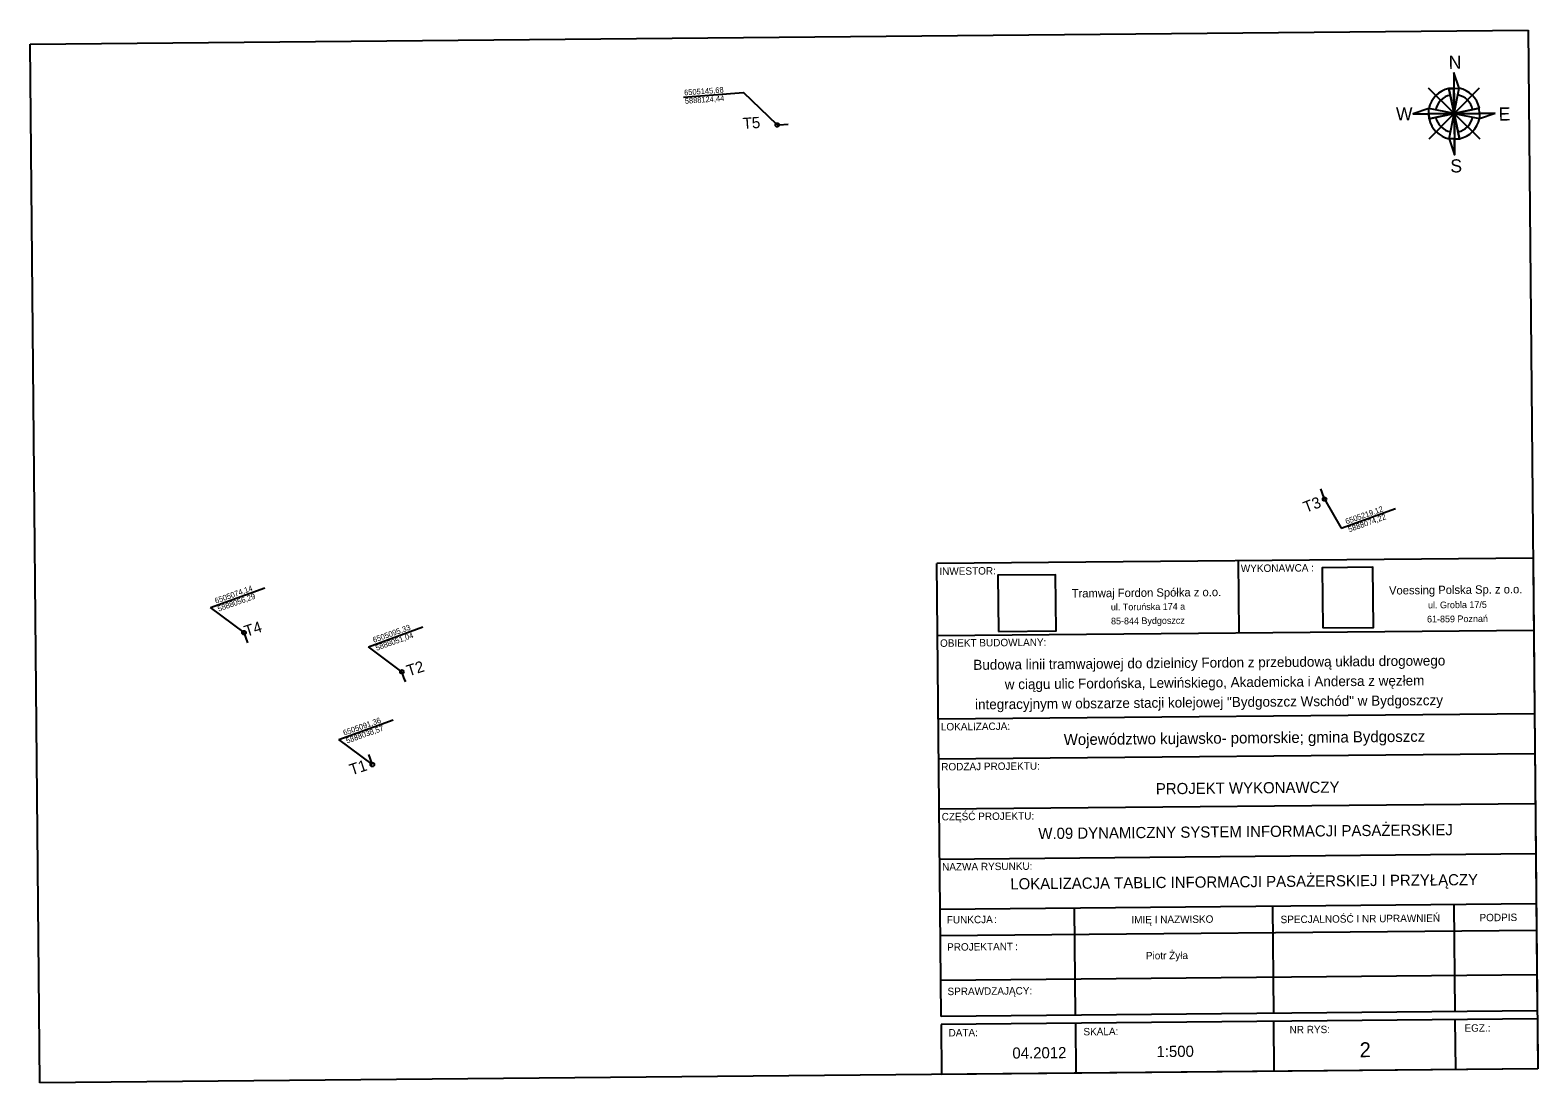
# Model space of a CAD drawing. Extents: x 6505045 to 6511721, y 5887996 to 5893535.
# Drawn here: x 6505045.4 to 6505247.7, y 5887995.8 to 5888137.2 of the extents above; entities that cross this region are included whole.
import ezdxf

# ---------------------------------------------------------------- set-up
doc = ezdxf.new("R2010")
doc.units = 0
for name, color, linetype in [('__legenda', 7, 'Continuous'), ('Default', 7, 'Continuous'), ('P_2 tablice LCD', 7, 'Continuous'), ('P_lokalizacja slupka', 7, 'Continuous'), ('P_opisy', 7, 'Continuous'), ('P_tabela', 7, 'Continuous'), ('P_wsporzedne', 7, 'Continuous'), ('P_znak północy', 7, 'Continuous'), ('SA_Linie-020', 7, 'Continuous'), ('SA_Stempel_Text-020', 7, 'Continuous'), ('SA_Stempel_Text-030', 7, 'Continuous'), ('SA_Stempel_Text-035', 7, 'Continuous'), ('SA_Unterschrift_Text', 7, 'Continuous')]:
    doc.layers.add(name, color=color, linetype=linetype)

msp = doc.modelspace()

# ---------------------------------------------------------------- linework, layer by layer
at = {"layer": '__legenda'}
msp.add_lwpolyline([(6505218.88, 5888056.93), (6505225.68, 5888056.99), (6505225.6, 5888065.06), (6505218.8, 5888065)], close=True, dxfattribs=at)
at = {"layer": 'Default'}
msp.add_lwpolyline([(6505175.35, 5888056.46), (6505183.09, 5888056.53), (6505183.02, 5888064.07), (6505175.28, 5888063.99)], close=True, dxfattribs=at)
at = {"layer": 'P_2 tablice LCD'}
for p, q in [((6505145.68, 5888124.44), (6505145.93, 5888124.45)), ((6505145.93, 5888124.45), (6505147.13, 5888124.53)), ((6505219.04, 5888074.46), (6505218.63, 5888075.59)), ((6505219.12, 5888074.22), (6505219.04, 5888074.46)), ((6505074.64, 5888054.93), (6505074.14, 5888056.29)), ((6505095.74, 5888049.91), (6505095.33, 5888051.04)), ((6505095.83, 5888049.68), (6505095.74, 5888049.91)), ((6505091.28, 5888038.81), (6505090.87, 5888039.93)), ((6505091.36, 5888038.57), (6505091.28, 5888038.81))]:
    msp.add_line(p, q, dxfattribs=at)
at = {"layer": 'P_lokalizacja slupka'}
for centre in [(6505145.68, 5888124.44), (6505219.12, 5888074.22), (6505074.14, 5888056.29), (6505095.33, 5888051.04), (6505091.36, 5888038.57)]:
    msp.add_circle(centre, 0.25, dxfattribs=at)
at = {"layer": 'P_tabela'}
for p, q in [((6505045.45, 5888135.29), (6505246.43, 5888137.17)), ((6505246.43, 5888137.17), (6505247.73, 5887997.72)), ((6505046.75, 5887995.85), (6505045.45, 5888135.29)), ((6505247.73, 5887997.72), (6505046.75, 5887995.85))]:
    msp.add_line(p, q, dxfattribs=at)
at = {"layer": 'P_wsporzedne'}
for p, q in [((6505133.12, 5888128.16), (6505141.15, 5888128.8)), ((6505145.68, 5888124.44), (6505141.15, 5888128.8)), ((6505219.12, 5888074.22), (6505221.33, 5888070.3)), ((6505221.33, 5888070.3), (6505228.64, 5888072.96)), ((6505069.65, 5888059.65), (6505076.95, 5888062.31)), ((6505074.14, 5888056.29), (6505069.65, 5888059.65)), ((6505090.84, 5888054.4), (6505098.14, 5888057.05)), ((6505095.33, 5888051.04), (6505090.84, 5888054.4)), ((6505086.87, 5888041.93), (6505094.17, 5888044.59)), ((6505091.36, 5888038.57), (6505086.87, 5888041.93))]:
    msp.add_line(p, q, dxfattribs=at)
at = {"layer": 'P_znak północy'}
for p, q in [((6505236.46, 5888131.49), (6505236.56, 5888120.45)), ((6505236.46, 5888131.49), (6505236.56, 5888120.45)), ((6505236.5, 5888125.97), (6505233.06, 5888129.36)), ((6505236.5, 5888125.97), (6505233.06, 5888129.36)), ((6505235.79, 5888129.34), (6505236.48, 5888129.35)), ((6505235.79, 5888129.34), (6505236.48, 5888129.35)), ((6505236.51, 5888125.98), (6505235.79, 5888129.34)), ((6505236.51, 5888125.98), (6505235.79, 5888129.34)), ((6505236.48, 5888129.35), (6505237.17, 5888129.36)), ((6505236.48, 5888129.35), (6505237.17, 5888129.36)), ((6505236.51, 5888125.99), (6505239.89, 5888129.42)), ((6505236.51, 5888125.99), (6505239.89, 5888129.42)), ((6505236.51, 5888125.98), (6505237.17, 5888129.36)), ((6505236.51, 5888125.98), (6505237.17, 5888129.36)), ((6505236.51, 5888125.98), (6505233.13, 5888126.63)), ((6505236.51, 5888125.98), (6505233.13, 5888126.63)), ((6505236.51, 5888125.98), (6505239.88, 5888126.69)), ((6505236.51, 5888125.98), (6505239.88, 5888126.69)), ((6505230.99, 5888125.92), (6505242.03, 5888126.02)), ((6505230.99, 5888125.92), (6505242.03, 5888126.02)), ((6505236.51, 5888125.99), (6505233.13, 5888122.53)), ((6505236.51, 5888125.99), (6505233.13, 5888122.53)), ((6505233.13, 5888125.94), (6505236.5, 5888125.97)), ((6505233.13, 5888125.94), (6505236.5, 5888125.97)), ((6505233.14, 5888125.25), (6505233.13, 5888125.94)), ((6505233.14, 5888125.25), (6505233.13, 5888125.94)), ((6505233.14, 5888125.25), (6505236.51, 5888125.98)), ((6505233.14, 5888125.25), (6505236.51, 5888125.98)), ((6505236.5, 5888125.97), (6505233.14, 5888125.25)), ((6505236.5, 5888125.97), (6505233.14, 5888125.25)), ((6505235.85, 5888122.59), (6505236.51, 5888125.98)), ((6505235.85, 5888122.59), (6505236.51, 5888125.98)), ((6505236.51, 5888125.99), (6505239.96, 5888122.59)), ((6505236.51, 5888125.99), (6505239.96, 5888122.59)), ((6505236.51, 5888125.98), (6505239.9, 5888125.31)), ((6505236.51, 5888125.98), (6505237.23, 5888122.6)), ((6505236.51, 5888125.98), (6505239.9, 5888125.31)), ((6505236.51, 5888125.98), (6505237.23, 5888122.6))]:
    msp.add_line(p, q, dxfattribs=at)
for points in [[(6505236.46, 5888131.49), (6505236.48, 5888129.35), (6505236.48, 5888129.35), (6505237.17, 5888129.36), (6505236.46, 5888131.49)], [(6505236.46, 5888131.49), (6505236.48, 5888129.35), (6505236.48, 5888129.35), (6505237.17, 5888129.36), (6505236.46, 5888131.49)], [(6505236.51, 5888125.99), (6505236.48, 5888129.35), (6505235.79, 5888129.34), (6505236.51, 5888125.98), (6505236.51, 5888125.99)], [(6505236.51, 5888125.99), (6505236.48, 5888129.35), (6505235.79, 5888129.34), (6505236.51, 5888125.98), (6505236.51, 5888125.99)], [(6505233.13, 5888125.94), (6505233.13, 5888126.63), (6505230.99, 5888125.92), (6505233.13, 5888125.94)], [(6505233.13, 5888125.94), (6505233.13, 5888126.63), (6505230.99, 5888125.92), (6505233.13, 5888125.94)], [(6505236.51, 5888125.98), (6505236.51, 5888125.97), (6505236.52, 5888125.97), (6505239.89, 5888126), (6505239.88, 5888126.69), (6505236.51, 5888125.98)], [(6505236.51, 5888125.98), (6505236.51, 5888125.97), (6505236.52, 5888125.97), (6505239.89, 5888126), (6505239.88, 5888126.69), (6505236.51, 5888125.98)], [(6505236.5, 5888125.97), (6505233.13, 5888125.94), (6505233.14, 5888125.25), (6505236.5, 5888125.97)], [(6505236.5, 5888125.97), (6505233.13, 5888125.94), (6505233.14, 5888125.25), (6505236.5, 5888125.97)], [(6505236.54, 5888122.59), (6505237.23, 5888122.6), (6505236.51, 5888125.96), (6505236.54, 5888122.59)], [(6505236.54, 5888122.59), (6505237.23, 5888122.6), (6505236.51, 5888125.96), (6505236.54, 5888122.59)], [(6505242.03, 5888126.02), (6505239.89, 5888126), (6505239.9, 5888125.31), (6505242.03, 5888126.02)], [(6505242.03, 5888126.02), (6505239.89, 5888126), (6505239.9, 5888125.31), (6505242.03, 5888126.02)], [(6505236.54, 5888122.59), (6505235.85, 5888122.59), (6505236.56, 5888120.45), (6505236.54, 5888122.59)], [(6505236.54, 5888122.59), (6505235.85, 5888122.59), (6505236.56, 5888120.45), (6505236.54, 5888122.59)]]:
    msp.add_lwpolyline(points, dxfattribs=at)
for centre, radius, start, end in [((6505236.51, 5888125.97), 3.45, 102.0474, 168.9738), ((6505236.51, 5888125.97), 3.45, 102.0474, 168.9738), ((6505236.51, 5888125.99), 2.53, 102.1671, 169.2958), ((6505236.51, 5888125.99), 2.53, 102.1671, 169.2958), ((6505236.51, 5888125.99), 2.53, 11.7816, 78.9353), ((6505236.51, 5888125.99), 2.53, 11.7816, 78.9353), ((6505236.51, 5888125.98), 3.45, 12.0554, 79.0163), ((6505236.51, 5888125.98), 3.45, 12.0554, 79.0163), ((6505236.51, 5888125.97), 3.45, 192.0538, 259.0158), ((6505236.51, 5888125.97), 3.45, 192.0538, 259.0158), ((6505236.51, 5888125.99), 2.53, 192.3917, 259.0318), ((6505236.51, 5888125.99), 2.53, 192.3917, 259.0318), ((6505236.51, 5888125.99), 2.53, 282.0081, 348.6723), ((6505236.51, 5888125.99), 2.53, 282.0081, 348.6723), ((6505236.51, 5888125.97), 3.45, 282.0538, 349.0163), ((6505236.51, 5888125.97), 3.45, 282.0538, 349.0163)]:
    msp.add_arc(centre, radius, start, end, dxfattribs=at)
at = {"layer": 'SA_Linie-020'}
for p, q in [((6505247.09, 5888066.29), (6505167.1, 5888065.55)), ((6505207.54, 5888065.93), (6505207.63, 5888056.27)), ((6505247.09, 5888066.29), (6505247.66, 5888005.5)), ((6505167.53, 5888019.13), (6505167.1, 5888065.55)), ((6505167.19, 5888055.89), (6505247.18, 5888056.64)), ((6505247.29, 5888045.41), (6505167.29, 5888044.66)), ((6505247.34, 5888040.04), (6505167.34, 5888039.29)), ((6505247.4, 5888033.32), (6505167.41, 5888032.57)), ((6505247.4, 5888033.32), (6505167.41, 5888032.57)), ((6505247.46, 5888026.6), (6505167.47, 5888025.85)), ((6505247.53, 5888019.88), (6505167.53, 5888019.13)), ((6505185.69, 5888004.93), (6505185.55, 5888019.3)), ((6505212.13, 5888019.55), (6505212.26, 5888005.17)), ((6505236.46, 5888019.77), (6505236.6, 5888005.4)), ((6505167.66, 5888004.76), (6505167.53, 5888019.13)), ((6505247.56, 5888016.32), (6505167.56, 5888015.57)), ((6505247.62, 5888010.36), (6505167.62, 5888009.61)), ((6505247.66, 5888005.5), (6505167.66, 5888004.76)), ((6505247.67, 5888004.44), (6505167.67, 5888003.7)), ((6505167.67, 5888003.7), (6505167.74, 5887996.98)), ((6505185.7, 5888003.87), (6505185.76, 5887997.15)), ((6505212.27, 5888004.11), (6505212.33, 5887997.39)), ((6505236.61, 5888004.34), (6505236.67, 5887997.62)), ((6505247.67, 5888004.44), (6505247.73, 5887997.72)), ((6505247.73, 5887997.72), (6505167.74, 5887996.98))]:
    msp.add_line(p, q, dxfattribs=at)

# ---------------------------------------------------------------- texts
at = {"layer": 'P_opisy'}
for s, rotation, p in [('T5', 3.877, (6505141.11, 5888123.89)), ('T3', 20.765, (6505216.6, 5888072.36)), ('T4', 17.9494, (6505074.46, 5888055.72)), ('T2', 17.9494, (6505096.23, 5888050.41)), ('T1', 17.9494, (6505088.56, 5888037.12))]:
    msp.add_text(s, height=1.501, rotation=rotation, dxfattribs=at).set_placement(p)
at = {"layer": 'P_wsporzedne'}
for s, rotation, p in [('6505145,68', 4.1827, (6505133.22, 5888128.41)), ('5888124,44', 4.1827, (6505133.31, 5888127.28)), ('6505219,12', 19.594, (6505222.06, 5888070.82)), ('5888074,22', 19.594, (6505222.44, 5888069.76)), ('6505074,14', 19.594, (6505070.37, 5888060.17)), ('5888056,29', 19.594, (6505070.75, 5888059.1)), ('6505095,33', 19.594, (6505091.56, 5888054.92)), ('5888051,04', 19.594, (6505091.94, 5888053.85)), ('6505091,36', 19.594, (6505087.59, 5888042.45)), ('5888038,57', 19.594, (6505087.97, 5888041.39))]:
    msp.add_text(s, height=0.751, rotation=rotation, dxfattribs=at).set_placement(p)
at = {"layer": 'P_znak północy'}
for s, p in [('N', (6505235.78, 5888131.97)), ('N', (6505235.78, 5888131.97)), ('W', (6505228.71, 5888125.05)), ('W', (6505228.71, 5888125.05)), ('E', (6505242.49, 5888125.03)), ('E', (6505242.49, 5888125.03)), ('S', (6505236, 5888118.06)), ('S', (6505236, 5888118.06))]:
    msp.add_text(s, height=1.76, rotation=0.535, dxfattribs=at).set_placement(p)
at = {"layer": 'SA_Stempel_Text-020'}
for s, p in [('INWESTOR:', (6505167.44, 5888064.03)), ('WYKONAWCA :', (6505207.89, 5888064.41)), ('OBIEKT BUDOWLANY:', (6505167.53, 5888054.38)), ('LOKALIZACJA:', (6505167.64, 5888043.15)), ('RODZAJ PROJEKTU:', (6505167.69, 5888037.78)), ('CZĘŚĆ PROJEKTU:', (6505167.75, 5888031.08)), ('NAZWA RYSUNKU:', (6505167.81, 5888024.34)), ('FUNKCJA', (6505168.44, 5888017.24)), (':', (6505174.77, 5888017.3)), ('IMIĘ I NAZWISKO', (6505193.21, 5888017.24)), ('SPECJALNOŚĆ I NR UPRAWNIEŃ', (6505213.22, 5888017.28)), ('PODPIS', (6505239.91, 5888017.53)), ('PROJEKTANT', (6505168.48, 5888013.58)), (':', (6505177.61, 5888013.66)), ('SPRAWDZAJĄCY:', (6505168.53, 5888007.62)), ('DATA:', (6505168.67, 5888002.07)), ('SKALA:', (6505186.77, 5888002.22)), ('NR RYS:', (6505214.43, 5888002.48)), ('EGZ.:', (6505237.89, 5888002.7))]:
    msp.add_text(s, height=1, rotation=0.535, dxfattribs=at).set_placement(p)
at = {"layer": 'SA_Stempel_Text-030'}
for s, height, p in [('2', 2, (6505223.84, 5887999.29)), ('04.2012', 1.5, (6505177.24, 5887999.1)), ('1:500', 1.5, (6505196.57, 5887999.3))]:
    msp.add_text(s, height=height, rotation=0.535, dxfattribs=at).set_placement(p)
at = {"layer": 'SA_Stempel_Text-035'}
for s, height, p in [('Budowa linii tramwajowej do dzielnicy Fordon z przebudową układu drogowego', 1.35, (6505172, 5888051.29)), ('w ciągu ulic Fordońska, Lewińskiego, Akademicka i Andersa z węzłem', 1.35, (6505176.22, 5888048.68)), ('integracyjnym w obszarze stacji kolejowej "Bydgoszcz Wschód" w Bydgoszczy', 1.35, (6505172.23, 5888045.98)), ('Województwo kujawsko- pomorskie; gmina Bydgoszcz', 1.5, (6505184.13, 5888041.19)), ('PROJEKT WYKONAWCZY', 1.5, (6505196.49, 5888034.58)), ('W.09 DYNAMICZNY SYSTEM INFORMACJI PASAŻERSKIEJ', 1.5, (6505180.72, 5888028.57)), ('LOKALIZACJA TABLIC INFORMACJI PASAŻERSKIEJ I PRZYŁĄCZY', 1.5, (6505176.96, 5888021.81))]:
    msp.add_text(s, height=height, rotation=0.535, dxfattribs=at).set_placement(p)
at = {"layer": 'SA_Unterschrift_Text'}
for s, height, p in [('Tramwaj Fordon Spółka z o.o.', 1.125, (6505185.19, 5888061)), ('Voessing Polska Sp. z o.o.', 1.125, (6505227.77, 5888061.4)), ('ul. Toruńska 174 a', 0.9, (6505190.45, 5888059.27)), ('ul. Grobla 17/5', 0.9, (6505233, 5888059.54)), ('85-844 Bydgoszcz', 0.9, (6505190.47, 5888057.39)), ('61-859 Poznań', 0.9, (6505232.87, 5888057.65)), ('Piotr Żyła', 1, (6505195.15, 5888012.42))]:
    msp.add_text(s, height=height, rotation=0.535, dxfattribs=at).set_placement(p)

doc.saveas('drawing.dxf')
